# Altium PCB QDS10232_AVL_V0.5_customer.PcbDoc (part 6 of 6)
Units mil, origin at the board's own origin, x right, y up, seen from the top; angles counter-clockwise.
Board outline 3500 x 3799 mil, 6 copper layers (Top Layer, GND, INT1, PWR1, PWR2, Bottom Layer), stack 78.834 mil thick; 254 components, 204 nets, 7039 pads, 595 vias.
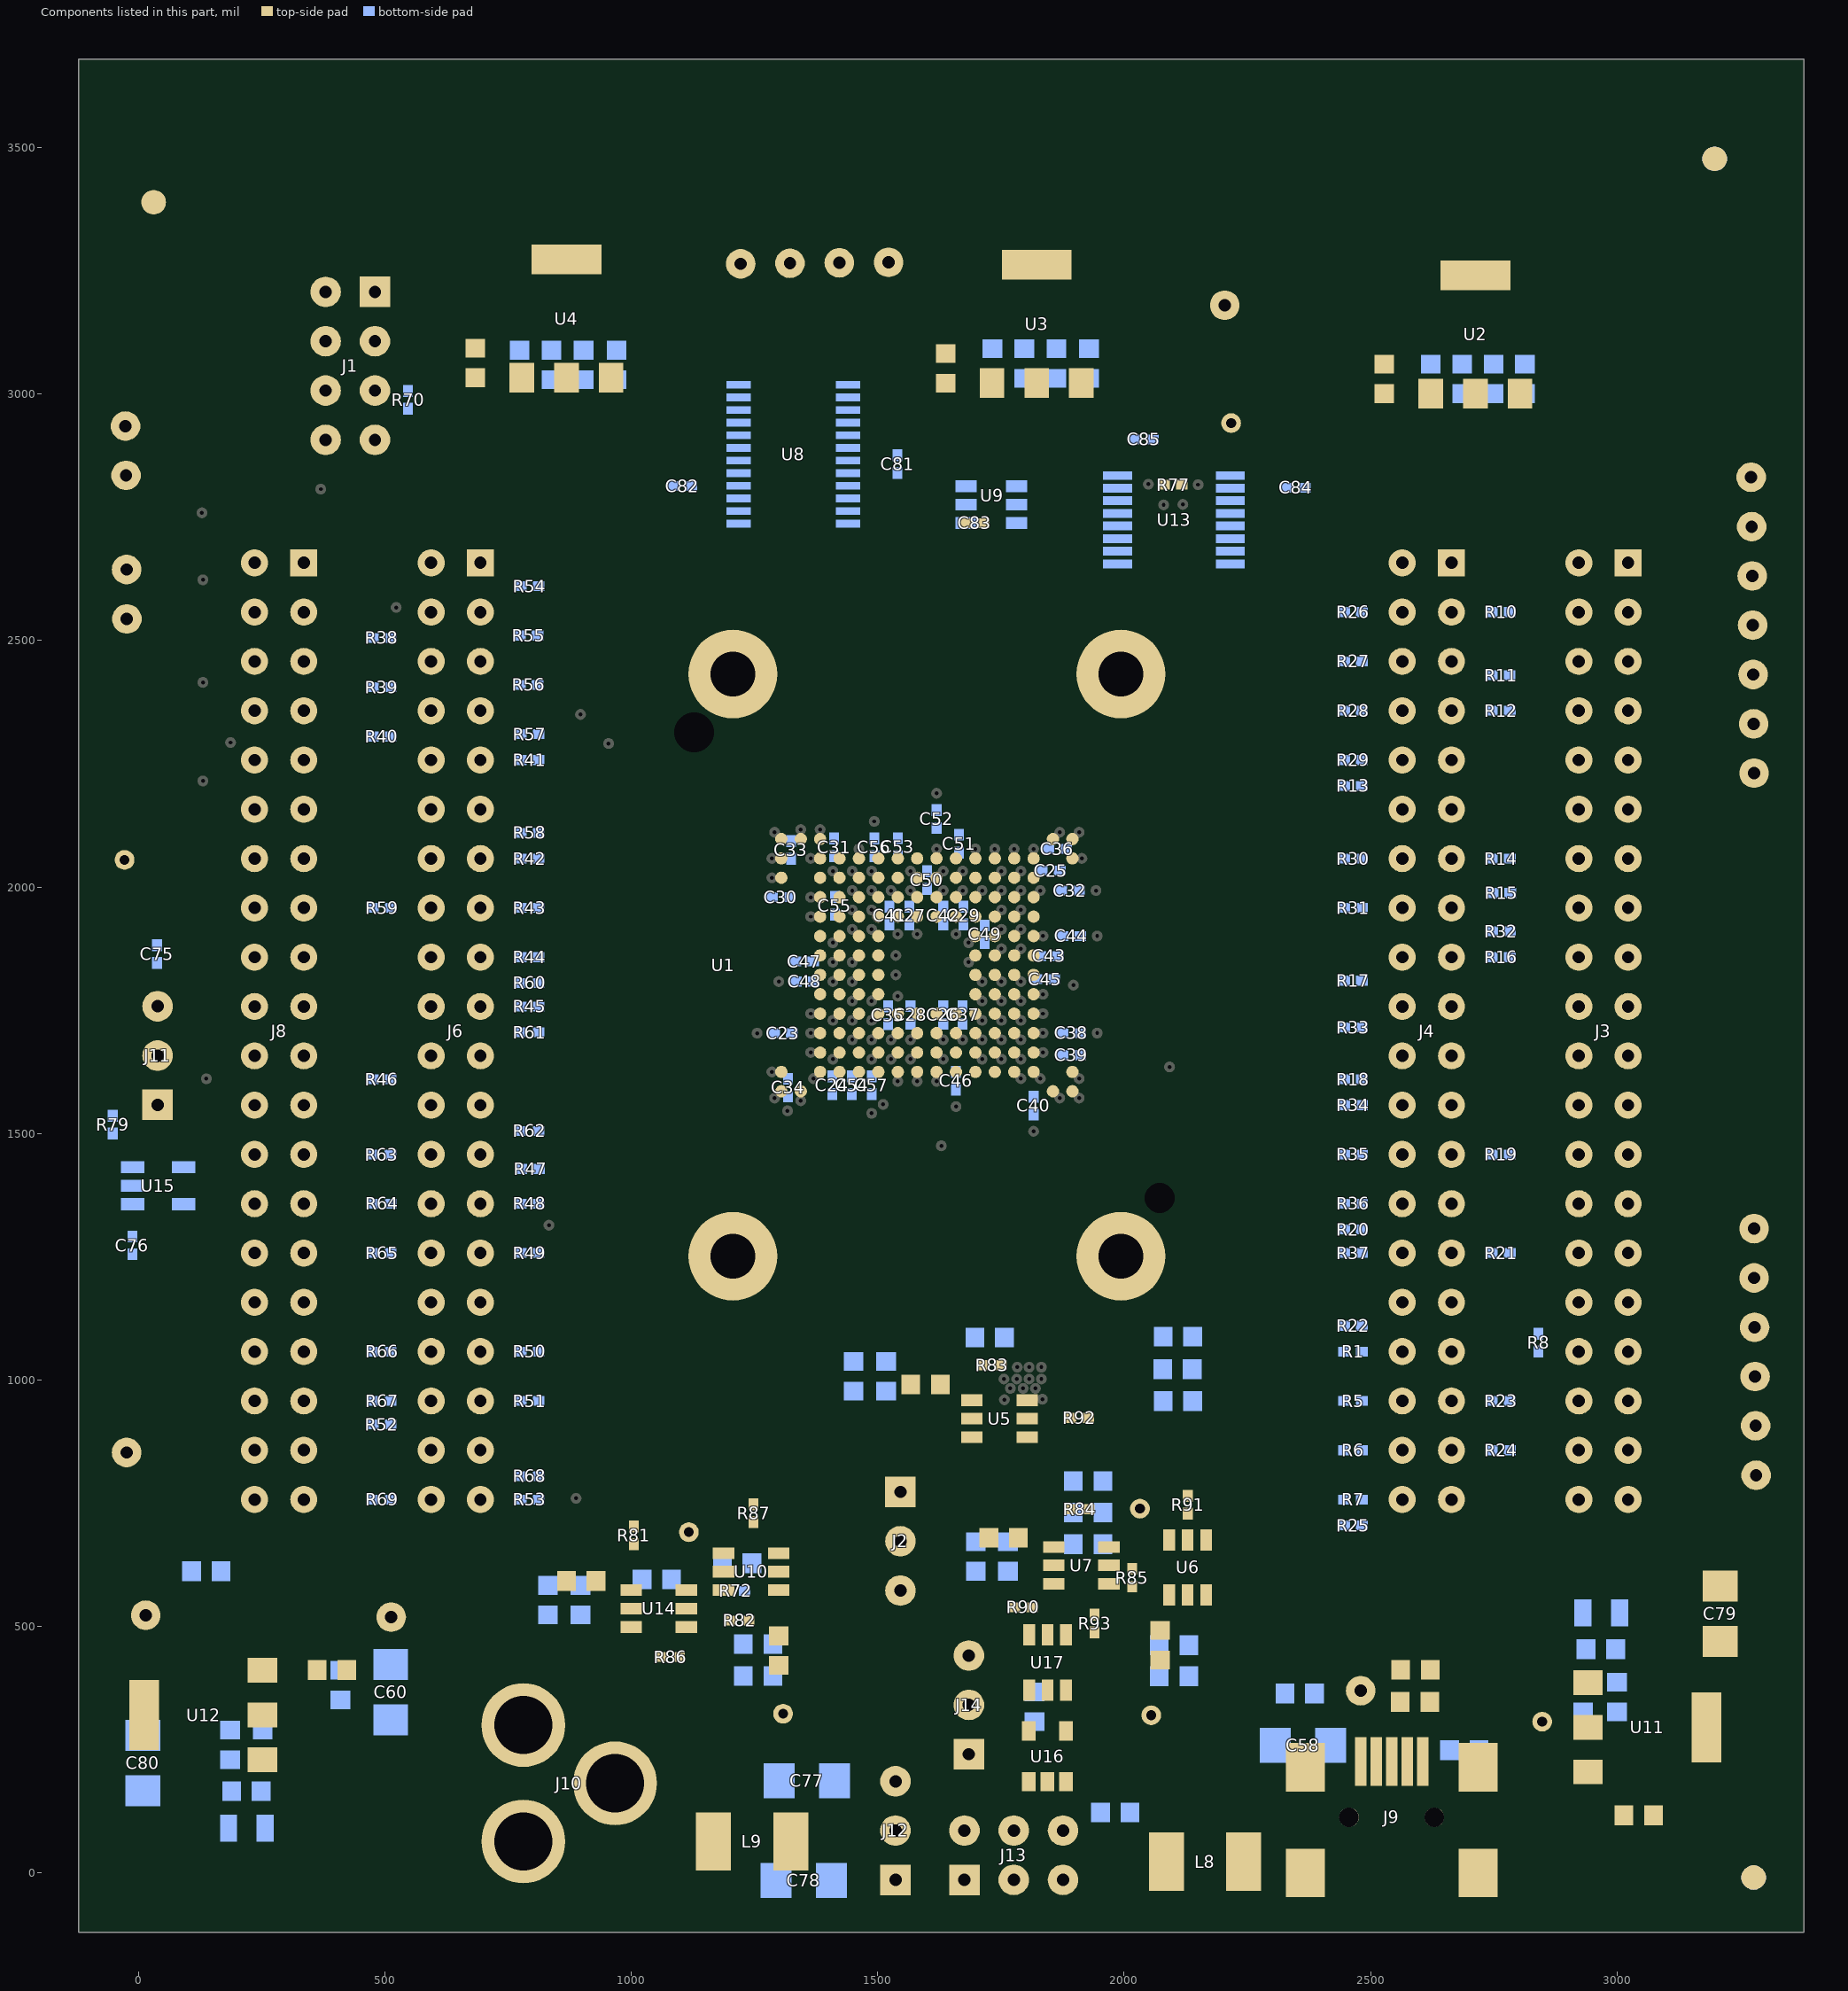
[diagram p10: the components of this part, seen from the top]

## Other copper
Top Layer:
  rectangle net VCCIO: 1267,282 1407,440
  region net VCC_REG: 3132,58 3265,191 3201,255 3068,122
  rectangle net VCC_REG: 3055,58 3133,198
  rectangle net NetL6_2: 2954,58 3035,147
  region net VCC_M: 2009.5,628.5 2024,643 1996.5,670.5 1982,656
  rectangle net VCC_M: 2003,605 2103,658
  rectangle net NetL2_1: 2003,471 2103,596
  rectangle net NetL3_2: 1765,651 1904,810
  rectangle net NetL5_1: 1225,461 1330,585
  region net VCCQ: 1166,535 1190,559 1156,593 1132,569
  rectangle net VCCQ: 1162,461 1214,582
  region net VCCQ: 1074.5,654.5 1098,678 1055.5,720.5 1032,697
  region net VCCQ: 1043,701 1093.5,751.5 1059,786 1008.5,735.5
  rectangle net VCCQ: 982,690 1088,740
  rectangle net VCCIO: 1381,737 1589,1043
  rectangle net VCC_M: 1738,947 1847,1043
  rectangle net NetL1_2: 1606,947 1727,1043
  region net VCC_REG: 3121,342 3216,437 3161,492 3066,397
  rectangle net VCC_REG: 3146,396 3269,505
  rectangle net VCC: 2105,2760 2166,2836
  rectangle net VCC_M: 2036,2760 2093,2836
  rectangle net NetJ9_6: 2329,87 2364,179
  rectangle net NetJ9_6: 2203,-49 2367,116
  rectangle net VCC_REG: 2813,258 3037,332
  region net GND: 1432,146 1283,146 1283,-25 1432,-25
  region net GND: 2143,114 1994,114 1994,-57 2143,-57
  rectangle net NetL6_2: 2803,58 2972,229.9
  rectangle net NetL6_2: 166,378 383,556
  rectangle net GND: 2147,193 2282,321
  rectangle net GND: 2147,302 2281,392
  rectangle net VCC_M: 1381,632 1589,716
  rectangle net VCC_REG: 3015,186 3270,405
  rectangle net VCCQ: 1059,694 1212,786
  rectangle net NetL4_2: 909,562 1027,681
  rectangle net GND_EXT: 383,142 609,346
  rectangle net VCCIO_REG: -39,243 115,554
  rectangle net +5V_EXT/(+3): 403,378 615,555
  rectangle net VCCIO_REG: 751,561.4 887.82,671.4
  rectangle net VCCEXT: 1972,152 2107,451
  rectangle net VCC_REG: 1619,649 1745,811
  rectangle net VCC_M: 1916,650 2103,810
  rectangle net GND: 1490,1810 1547,1873
  pour cut-out: 1240,732 1294.45,755.38 1285,720 1248,712
  pour cut-out: 1323,637 1318,595 1242,593 1245,612 1267,636
  pour cut-out: 1000,451 1043,429 1077,439 1114,482 1071,502 1004.64,483.2
  pour cut-out: 1014,562 958,559 945,545 979,507 1018,456 1046,455 1061,465.98 1063,557 1040,578
  pour cut-out: 654.21,615.79 628,551 693,548 687.33,582.67
  pour cut-out: 980,549 947,553 912,540 911,499 961,485 996,492 1012,525
  pour cut-out: 1450,624 1457,585 1477,590 1487,619 1472,626
  pour cut-out: 1821,376 1914.4,371 1933,362 1909,299 1867,255 1812,256 1806.9,326.07
  pour cut-out: 1846,644 1848,602 1886,606 1894,630 1875,651
  pour cut-out: 1951,505 1966,451 1981,465 1968,510
  pour cut-out: 1938,508 1896,474 1896,508 1920,519
  pour cut-out: 1478.64,1584.64 1670.7,1584.3 1651,1637 1526,1636
  pour cut-out: 1860.43,1821.76 1851,1600 1802.95,1559.46 1737.5,1564.16 1753,1663 1776.87,1703.65 1815,1799
  pour cut-out: 1859,2018.61 1859,1861.13 1826,1877 1844,1996
  pour cut-out: 1718,2100.12 1820,2099 1848.72,2018.61 1751.06,2032.18 1718,2052.72
  pour cut-out: 1588,2103 1678.76,2104.76 1658.76,2084.76 1580.02,2083.27
  pour cut-out: 1533.86,1986.03 1422.54,1979.24 1396,1895 1438,1750 1455.12,1736.24 1533.86,1696.87 1726,1687 1783.65,1696.87 1799,1771 1777,1919 1751.06,1992.81 1632.95,1992.81
  pour cut-out: 566.46,1257.56 547,1211 596,1219 604,1228
  pour cut-out: 456,1344 475,1303 439,1321 440,1331
  pour cut-out: 208.19,1257.56 191,1219 227,1215 235.69,1230.06
  pour cut-out: 193,1301 204,1268 229,1279 229,1305
  pour cut-out: 453,1301 446,1268 433,1248 394,1242 426,1331
  pour cut-out: 216.25,1338.11 199,1317 281,1313 360,1313 344,1341 242,1352
  pour cut-out: 355.14,1238.11 383,1213 392,1228 377,1251
  pour cut-out: 1124,479 1154,459 1155,476 1128.65,487.19
  pour cut-out: 2438,1296 2403,1268 2395,1247 2408,1215 2448,1246 2455,1279
  pour cut-out: 2413,1342 2438,1310 2447,1348 2411.64,1357.56
  pour cut-out: 2362,1469 2415,1469 2447,1437 2438,1428 2412,1428 2403,1419 2382,1440 2373,1440
  pour cut-out: 2615,2964 2634,2938 2641,2943 2638,2963
  pour cut-out: 2546,3029 2589,3043 2599,3003 2589,2960 2543,2977
  pour cut-out: 2636,3038 2682,3053 2685,3030 2668,3010 2651,3013
  pour cut-out: 1724,2984 1749,2949 1754,2990
  pour cut-out: 1754,3061 1792,3073 1790,3052 1761,3041
  pour cut-out: 766,2997 795,2968 801,2992 790,3003
  pour cut-out: 698,3059 744,3074 747,2992 703,3009 699,3035
  pour cut-out: 794,3074 838,3084 834,3060 799,3054
  pour cut-out: 805,1898.92 721,1848 746,1825 808,1843 814,1875
  pour cut-out: 2369,2249 2401,2216 2467,2200 2458,2245 2411.64,2257.56
  pour cut-out: 2898,2545 2859,2516 2899,2461 3014,2459 3047,2465 3073,2506 3053,2545 3013,2555 2922.31,2557.56
  pour cut-out: 2977,423 3024,413 3003,394 2957,403
  pour cut-out: 2877,375 2855,339 2904,337 2912,353
  pour cut-out: 2120,961 2100,923 2072,947 2083,962
  pour cut-out: 189,289 212,248 308,248 290,298 227,306
  pour cut-out: 211,1049 178,1009 176,986 253,961 284,996 296,1028 252,1056
  pour cut-out: 385,1409 347,1376 344,1345 404,1337 413,1363
  pour cut-out: 382,1500 344,1477 343,1440 387,1417 397,1469
  pour cut-out: 458,1568 487,1557 477,1530 450,1528 441.52,1546.52 448,1563
  pour cut-out: 512,1479 605,1454 669,1456 693.96,1457.56 736,1503 671,1529 523,1534
  pour cut-out: 743,1502 786,1463 823,1481 796,1528
  pour cut-out: 861,1415 850,1368 844,1345 791,1304 789,1389 819,1431
  pour cut-out: 565,1348 545,1312 543,1297 566,1272 604,1293 601,1328
  pour cut-out: 624,1348 692,1347 696,1313 601,1306 608,1342
  pour cut-out: 716,1341 779,1339 779,1323 712,1331
  pour cut-out: 731,1201 753,1156 794,1175 803,1206 754,1220
  pour cut-out: 483,1151 504,1119 480,1106 466,1135
  pour cut-out: 97,564 173,565 161,534 138,518 100,522
  pour cut-out: 321,376 286,333 267,364 274,386
  pour cut-out: 356,377 377,333 396,340 396,378
  pour cut-out: 878,343 947,278 899,248 846,285
  pour cut-out: 836,460 797,420 787,449 802.6,467.4
  pour cut-out: 810,561 788,523 772,505 759,546 783,567
  pour cut-out: 714,667 756,633 768,681 755,701 719,702 709,686
  pour cut-out: 900,730 928,630 852,618 867,707
  pour cut-out: 1054,661 1012,626 1006,564 1084,533 1093,596 1080,638
  pour cut-out: 1223,696 1225,666 1214,665 1210,674
  pour cut-out: 1645,649 1588,591 1538,647 1577,668
  pour cut-out: 1583,857 1640,816 1622,773 1546,773
  pour cut-out: 2825,53 2756,6 2760,49 2795,63
  pour cut-out: 3044,181 2967,149 2975,191 3014,197
  pour cut-out: 2810,304 2751,273 2757,241 2801,241 2819,255
  pour cut-out: 2681,296 2702,270 2690,257 2673,270
  pour cut-out: 2667,281 2620,280 2616,174 2680,172 2674,273
  pour cut-out: 2578,179 2674,179 2673,170 2572,171
  pour cut-out: 2376,300 2356,266 2397,263 2403,288
  pour cut-out: 2591,390 2592,380 2589,376 2587,382
  pour cut-out: 2504,475 2550,442 2533,424 2491,433
  pour cut-out: 2966,800 2933,775 2919,746 2949,694 2981,726 2974,772
  pour cut-out: 2898,950 2871,915 2869,898 2892,865 2940,861 2975,918 2940,943 2929,950
  pour cut-out: 2523,807 2547,761 2657,767 2711,812 2710,820 2687,850 2643,852 2544,855 2515,817
  pour cut-out: 2443,810 2414,767 2394,792 2402,812
  pour cut-out: 2430,852 2443,821 2432,813 2409,837
  pour cut-out: 2356,914 2327,891 2360,876 2368,901.2
  pour cut-out: 2407,1039 2368,1033.6 2380,1054 2398,1056
  pour cut-out: 2584,1545 2671,1547 2692,1543 2707,1511 2724,1475 2664.04,1457.56 2579,1454 2532,1467 2513,1506 2568,1537
  pour cut-out: 2532,1544 2515,1519 2561,1513 2562,1544
  pour cut-out: 2352,1565 2401,1572 2431,1553 2443,1515 2380,1536
  pour cut-out: 2213,1572 2176,1505 2242,1504 2244,1540
  pour cut-out: 1323,1761 1322,1687 1360,1691 1368,1733 1351,1766
  pour cut-out: 1308,1839 1251,1827 1266,1786 1349,1778 1375,1813
  pour cut-out: 1325,1675 1376,1550 1406.27,1608.65 1383.17,1664.28 1361,1677
  pour cut-out: 1203,1551 1222,1513 1180,1515 1184,1538 1190,1551
  pour cut-out: 1503,2158 1467,2155 1458.14,2124.86 1491,2094 1531,2101 1521,2148
  pour cut-out: 1383,2074 1417,2096 1417,2074 1398,2060
  pour cut-out: 1344,2062 1323,2022 1338.61,2018.61 1360.89,2018.61 1374,2048
  pour cut-out: 1155,1950 1171,1899 1197,1920 1193,1962
  pour cut-out: 853,1943 812,1920 815,1952 832,1955
  pour cut-out: 539,1796 566,1763 608,1756 683,1756 713,1757 760,1781 738,1808 578,1803
  pour cut-out: 532,1833 583,1847 678,1853 723,1846 742,1812 645,1805 542,1805
  pour cut-out: 460,1960 454,1905 426,1927 433,1961
  pour cut-out: 835,2101 787,2112 803,2126 827,2126
  pour cut-out: 786,2194 796,2162 824,2175 818,2198
  pour cut-out: 330,2534 332,2477 359,2507 346,2533
  pour cut-out: 924,2636 875,2643 827,2619 882,2560 955,2622
  pour cut-out: 1482,2726 1433,2716 1440,2731 1469,2748
  pour cut-out: 1398,2893 1374,2890 1357,2859 1395,2829 1426,2837 1424,2880
  text "TOP" at 4320,1517 h65
GND:
  text "GND1" at 4328,1218.56 h65
PWR1:
  text "POWER 1" at 5601,1219 h65
INT1:
  pour cut-out: 2685,618 2738,600 2832,499 2832,-97 2803,-104 2805,-21 2782,-7 2791,16 2808,33 2805,414 2681,578 2686,608
  pour cut-out: 2271,191 2247,150 2267,136 2289,138 2295,146 2295,162 2290,170 2278,173 2277,184
  pour cut-out: 2274,476 2290,466 2293,452 2289,443 2282,437 2270,433 2255,447 2256,464 2270,477 2271,477
  pour cut-out: 2270,592 2270,538 2297,541 2301,552 2301,564 2296,571 2290,575 2276,575
  pour cut-out: 1348,777 1312,741 1333,722 1359,729 1364,744 1358,758 1349,770
  pour cut-out: 1938,951 1999,951 1995,909 1960,903 1941,939
  pour cut-out: 2156.73,1007.27 2117,939 2184,944 2186,972
  pour cut-out: 2583,744 2575,661 2479,678 2540,744
  pour cut-out: 1959,1637 1888,1640 1896,1569 2148,1546 2240.76,1537 2239,1617 2116,1662
  pour cut-out: 906,2383 797,2316.56 797,2373.95 870,2416
  pour cut-out: 1918.96,1931 1919.82,1868 1862,1868 1859,1910
  pour cut-out: 1693,1945 1617,1929.66 1627,1765 1653,1722 1709,1721 1771,1745.51 1772,1898 1771,1934.01
  pour cut-out: 1467.78,1959.35 1390,1908 1418.7,1867 1498.32,1856.32 1534,1927
  pour cut-out: 1513,1852 1448.34,1808.2 1461.66,1742.78 1455,1683 1527.08,1690.09 1563,1719 1582.5,1838.5 1573,1851
  pour cut-out: 2091.14,1662 2067,1654 2061,1617 2115.13,1608 2124,1622 2116,1662
  pour cut-out: 1969.79,1608 1956.65,1537 1837,1579 1879,1646 1904,1642
  pour cut-out: 2029,1441 2035,1401 2093.72,1390.58 2111,1425 2109,1456
  pour cut-out: 2899,1254 2873,1211 2958.93,1195.07 2955,1256
  pour cut-out: 2895,1554 2866.88,1508 2855,1491 2915,1464 2941,1457 2963,1507 2956,1540
  pour cut-out: 2933,1582 2970,1606 3016,1589 3018,1533 2970,1519 2936,1522 2938,1564
  pour cut-out: 2976,1801 3014,1784 3015,1735 2979,1713 2965,1760
  pour cut-out: 2878,1708 2967,1709 2964,1732 2880,1732
  pour cut-out: 2442,2094 2417,2072 2416,2042 2425,1968 2448,1972 2445,2079
  pour cut-out: 2365,2349 2388,2300 2421,2393 2402,2410 2372,2367
  pour cut-out: 2408,2186 2438,2162 2443,2190 2435,2212
  pour cut-out: 2780.64,2465.28 2792,2376 2817,2401 2819,2446
  pour cut-out: 2847.22,2326.78 2778,2305 2787,2347 2816.44,2357.56
  pour cut-out: 2507,2495 2535,2455 2575,2457 2648,2453 2693,2455 2721,2500 2590,2515
  pour cut-out: 2467,2495 2439.32,2429.88 2411.64,2457.56 2431,2495
  pour cut-out: 2364,2548 2405,2501 2425,2559 2386,2566
  pour cut-out: 885,2644 873,2591 846,2627 849,2650
  pour cut-out: 385,1211 189,1209 208,1245 344,1244 389,1235 374,1223
  pour cut-out: 446,1239 414,1214 419,1247 430,1253
  pour cut-out: 416,1098 446,1077 441.56,1057.56 439,1040 417,1019 408,1060 409,1070
  pour cut-out: 192,1106 230,1087 292,1099 330,1086 319,1056 214,1062 192,1069 191,1084
  pour cut-out: 369,1085 390,1102 385,1063 362,1049 348,1069 362,1079
  pour cut-out: 421,992 447,974 429,965 412,973
  pour cut-out: 438,900 383,876 390,908 406,925
  pour cut-out: 2512,999 2535,965 2565,983 2547,1008
  pour cut-out: 2715,1010 2694,967 2673,983 2674,995
  pour cut-out: 2749,1021 2768,996 2840,1008 2817,1031 2771,1031
  pour cut-out: 2519,1014 2552,1046 2572,1050 2677,1052 2725,1031 2711,1010 2576,994
  pour cut-out: 2510,1307 2547,1350 2664.04,1357.56 2723,1310 2677,1278 2555,1281
  pour cut-out: 2514,1508 2547,1464 2669,1464 2687,1467 2711,1519 2629,1546
  pour cut-out: 1886,1906 1901,1872 1859,1868 1855.5,1890.5
  pour cut-out: 1489,1613 1530,1599 1529,1622 1512.72,1636.36
  pour cut-out: 1339,1642 1330,1634 1353,1607 1378,1598 1417,1614 1372,1657
  pour cut-out: 1307,1676 1349,1730 1408.97,1729.46 1420,1704 1390,1654 1327,1654
  pour cut-out: 1781,1557 1757,1518 1742,1535 1734,1558 1769,1572
  pour cut-out: 1904,1657 1882,1613 1841,1633 1851,1660 1873,1674
  pour cut-out: 1910,1597 1832.8,1586 1841,1538 1893,1546 1937,1556 1939,1585
  pour cut-out: 2436,1497 2421,1459 2400,1488 2416,1500 2428,1507
  pour cut-out: 648,512 600,491 594,431 712,362 695,464 679,507
  pour cut-out: 716,1706 759,1680 782,1712 760,1734
  pour cut-out: 1407,2974 1471,2951 1475,2936 1450.5,2930.5 1399,2948
  pour cut-out: 1267,2918 1234,2917 1227,2865 1288,2852 1314,2882 1308,2910
  pour cut-out: 1392,2892 1352.64,2876.49 1372.82,2839 1404.5,2839 1423,2861
  pour cut-out: 517,2498 476,2494 482,2425 560,2422 593.96,2457.56 573,2498
  pour cut-out: 936,2803 963,2769 915,2767 920,2791
  pour cut-out: 545,2867 575,2824 533,2821 527,2837
  pour cut-out: 236,2528 236,2484 260.35,2482.21 258,2534
  pour cut-out: 233,2433 233,2385 249,2388 259,2430 251,2436
  pour cut-out: 228,2332 227,2280 251,2291 250,2336
  pour cut-out: 459,2361 515,2346 505,2321 451,2312
  pour cut-out: 252,2239 294.5,2199.5 295,2243 261,2248
  pour cut-out: 419,2249 460,2234 465,2275 424,2270
  pour cut-out: 275,2106 237,2079 321,2052 327,2068 294,2104
  pour cut-out: 231,2036 234,1976 250,1989 245,2037
  pour cut-out: 232,1932 233,1883 251,1891 259,1932
  pour cut-out: 263,1859 304,1858 310,1867 271,1870 257,1863
  pour cut-out: 390,1911.87 438,1868 449,1901 410,1923
  pour cut-out: 832,2498 783,2484 795,2508 831,2509
  pour cut-out: 1072,2321 1025,2300 1187,2224 1209,2230 1172,2281
  pour cut-out: 1078,2207 1060,2178 1095,2177 1098,2194
  pour cut-out: 1527,2133 1495,2098 1520,2088 1541,2101 1533,2130
  pour cut-out: 1600,2142 1643,2150 1646,2130 1612,2121
  pour cut-out: 1654,2118 1760,2106 1737.5,2077.17 1666,2088
  pour cut-out: 1829,2069 1839,2033 1790.43,2032.18 1794,2049
  pour cut-out: 1872,2017 1876,1965 1854,1960 1846,1991 1856,2011
  pour cut-out: 1864,1904 1886,1869 1853,1859 1845,1887
  pour cut-out: 1938,1742 1887,1720 1939,1667 1991,1682 2004,1717 1985,1745
  pour cut-out: 2156,1872 2180,1832 2130,1834 2131,1845
  pour cut-out: 2527,2002 2537,2040 2586,2060 2713,2056 2744,2036 2650,1985 2543,1994
  pour cut-out: 2787,2107 2876,2103 2870,2077 2777,2088
  pour cut-out: 2793,1799 2863,1769 2857,1830 2796,1827
  pour cut-out: 2833,1209 2801.29,1166.98 2791,1200 2799,1215
  pour cut-out: 3050,1055 3093,1032 3085,1018 3036,1025
  pour cut-out: 2896,949 2874,908 2947,912 2946,934
  pour cut-out: 2901,1050 2873,1017 2893,975 2918,980 2928,1020
  pour cut-out: 2965,1109 2929,1077 2968,1068 2973,1083
  pour cut-out: 2685,960 2709,902 2691,868 2638,910
  pour cut-out: 2518,898 2535,871 2551,871 2572,926 2562,943 2521,918
  pour cut-out: 2502,796 2537,758 2643,747 2698,756 2718,800 2689,853 2577,862 2529,851 2509,802
  pour cut-out: 663,583 640,544 666,518 701,532 696,556
  pour cut-out: 892,377 857,324 826,373 846,390
  pour cut-out: 189,1408 208,1448 248,1460 335.69,1457.56 321,1395 243,1376
  pour cut-out: 353,1569 441.52,1610 448,1581 372,1532
  pour cut-out: 328,1489 335,1538 355,1518 359,1470 354,1462
  pour cut-out: 858,1043 880,1006 935,979 936,1033 885,1064
  pour cut-out: 901,689 888,639 863,657 867,671
  pour cut-out: 873,625 793,577 788,609 812,635
  pour cut-out: 794,567 777,514 739,549 750,566
  text "INTERNAL1" at 4341,1369 h65
PWR2:
  text "POWER 2" at 5603,1063 h65
Bottom Layer:
  rectangle net VCCEXT: 1440,336 1604,609
  rectangle net VCCIO: 1266,282 1407,520
  region net VCCIO_REG: 114,243 147,276 130,293 97,260
  region net +5V_USB/(+3): 2618,259 2678,319 2592,405 2532,345
  rectangle net VCCIO: 1381,738 1589,999
  rectangle net GND_EXT: 387,137 615,370
  rectangle net VCC: 2106,2760 2166,2836
  rectangle net VCC_M: 2036,2760 2091,2836
  rectangle net NetL6_2: 149,379 370,635
  rectangle net GND: 2115,178 2346,321
  rectangle net GND: 2248,303 2346,392
  region net GND: 2226,256 2305,335 2248,392 2169,313
  rectangle net VCC_M: 1400,632 1589,716
  rectangle net +5V_USB/(+3): 2366,289 2609,533
  rectangle net VCC_REG: 3044,325 3268,405
  rectangle net VCC_REG: 3007,186 3268,343
  region net VCCIO_REG: 142,298 167.5,323.5 107,384 81.5,358.5
  rectangle net VCCIO_REG: -41,243 128,635
  rectangle net GND: 1225,603 1360,652
  rectangle net GND_EXT: 458,235 569,343
  rectangle net GND_EXT: 387,291 435,370.56
  rectangle net +5V_EXT/(+3): 390,388 616,560
  rectangle net VCCIO_REG: 63,269 288,338
  rectangle net VCC_REG: 2823,261 3152,346
  rectangle net +5V_USB/(+3): 2368,177 2679,320.45
  rectangle net GND: 752,3070 1003,3168
  rectangle net GND: 2580,3045 2851,3132
  rectangle net GND: 1695.39,3064 1968,3184
  rectangle net GND: 1204.82,366.4 1246.82,520.4
  rectangle net VCCQ: 1060.82,545.4 1205.82,785
  rectangle net VCCIO_REG: 752,563.4 939.82,661.4
  rectangle net GND: 804.82,496.4 972.53,545.4
  rectangle net GND: 2112,361 2178,536
  rectangle net GND: 1662,584 1829.71,633
  rectangle net VCC_REG: 1617,651 1797,812
  rectangle net GND: 1835,647 1916,819
  rectangle net GND: 1509,1746 1696,1936
  rectangle net VWR: 752,2952.93 1002.7,3062.93
  rectangle net VDD: 1703.7,2941.93 1956.7,3051.93
  rectangle net VPPW: 2593.7,2920.64 2846.7,3030.64
  pour cut-out: 1433,552 1401,532 1419,511 1430,509 1436,521
  pour cut-out: 1459,324 1411,300 1415,331 1438,330
  pour cut-out: 2694,1560 2732,1508 2705,1495 2658,1526
  pour cut-out: 2638,1950 2616.48,1910 2668,1910 2670,1932
  pour cut-out: 2837,1902 2835,1864 2819,1874 2817,1893
  pour cut-out: 2826,1980 2825,1916 2799,1939 2817,1974
  pour cut-out: 1683,1718 1752,1704 1751.06,1690.09 1672.32,1690.09
  pour cut-out: 1762,1773 1765,1701 1783,1700 1796,1750 1790.43,1768.83
  pour cut-out: 1714,1908 1740,1874 1760,1892 1763,1916
  pour cut-out: 1455,1792 1413,1791 1418,1808 1433,1816
  pour cut-out: 1368,1755 1448,1745 1419,1713 1358,1718
  pour cut-out: 645,1497 663,1461 683,1467 695,1496
  pour cut-out: 856,1488 854,1443 829,1458 836,1488
  pour cut-out: 753,1599 764,1518 724,1537 726,1579
  pour cut-out: 512,1656 496,1626 535,1618 552,1627
  pour cut-out: 177,1752 260,1766 351,1757 386,1715 278,1711 182.5,1733.5
  pour cut-out: 294,1901 316,1865 358,1865 399,1896 360,1919 315,1917
  pour cut-out: 403,1982 252,1975 272,1942 416,1947
  pour cut-out: 538,1892 561,1858 581,1871 579,1898
  pour cut-out: 581,1837 578,1780 601,1785 605,1820
  pour cut-out: 867,1846 870,1762 836,1789 838,1833
  pour cut-out: 906,1880 864,1862 859,1892
  pour cut-out: 908,1992 901,1916 874,1924 889,1994
  pour cut-out: 1240,1883 1205,1839 1183,1875 1220.06,1886.94
  pour cut-out: 1023,2096 1007,2066 1049.44,2057.56 1061,2071
  pour cut-out: 865,2096 882,2065 833,2085 833,2097
  pour cut-out: 2530,1855 2486,1820 2611.6,1810 2589,1851 2564.04,1857.56
  pour cut-out: 2469,1798 2485,1757 2506.56,1757.56 2514,1790
  pour cut-out: 2650,1739 2578,1756 2639,1761 2664.04,1757.56
  pour cut-out: 2688,1839 2679,1785 2651,1801 2661,1843
  pour cut-out: 2581,2270 2638,2271 2637,2245 2588,2240
  pour cut-out: 2035,2903 2070,2836 2000,2839 2003,2890
  pour cut-out: 1634,2722 1587,2717 1589,2733 1626,2739
  pour cut-out: 1110,2873 1100,2832 1132,2832 1143,2847
  pour cut-out: 1182,2725 1158,2660 1205,2662 1217,2708 1211,2721
  pour cut-out: 1573,2701 1582,2663 1552,2664 1548,2679
  pour cut-out: 1274,2723 1333,2715 1331,2731 1297,2748
  pour cut-out: 1377,2824 1331,2805 1357,2791 1386,2794
  pour cut-out: 1502,2730 1520,2708 1494,2689 1466,2710 1470,2726
  pour cut-out: 1415,2886 1418,2845 1541,2853 1501,2887 1463.86,2890.54
  pour cut-out: 573,2566 522,2522 573,2504 612,2514
  pour cut-out: 716,2657 771,2626 742,2609 717,2620
  pour cut-out: 776,2602 776,2522 732,2538 749,2593
  pour cut-out: 776,2499 774,2423 753,2427 753,2490
  pour cut-out: 767,2401 776,2310 730,2323 759,2400
  pour cut-out: 511.92,2305.12 567,2249 591,2288 575,2304
  pour cut-out: 536,2487 465,2476 477,2431 571,2417 585,2451
  pour cut-out: 291,287 313,247 299,240 263,257
  pour cut-out: 322,374 297,331 265,358 278,377
  pour cut-out: 673,227 611,196 628,229 653,239
  pour cut-out: 1595,855 1634,814 1602,812 1585,829
  pour cut-out: 3042,184 2988,145 2981,186
  pour cut-out: 2374,171 2374,-20 2715,-19 2710,169 2656,175 2494,197 2408,188
  pour cut-out: 2639,87 2720,61 2698,99
  pour cut-out: 2578,177 2597,133 2638,127 2624,182
  pour cut-out: 2655,352 2713,348 2703,324 2683,322 2663,332
  pour cut-out: 2874,390 2781,352 2806,330 2879,339 2910,363
  pour cut-out: 2590,772 2643,772 2641,747 2583,743
  pour cut-out: 2591,1041 2645,1043 2639,1064 2598,1070
  pour cut-out: 2396,1113 2411.64,1057.56 2441,1080 2428,1110
  pour cut-out: 2662,931 2657,871 2690,883 2695,935
  pour cut-out: 2611.6,1305.12 2585,1259 2572,1297
  pour cut-out: 2389,1319 2395,1264 2424,1273 2428.94,1305.12
  pour cut-out: 2712,1394 2695,1363 2681,1382 2686,1403
  pour cut-out: 2771,1443 2748,1399 2731,1422 2733,1445
  pour cut-out: 2822,1441 2856,1415 2847,1452 2816.44,1457.56
  pour cut-out: 1745,1860 1740,1813 1762,1812 1778,1845
  pour cut-out: 1575,1745 1622,1745 1616,1723 1577,1719
  pour cut-out: 1710,1638 1672,1622 1677,1641 1696,1649
  pour cut-out: 1899,1691 1898,1675 1881,1675 1879,1684
  pour cut-out: 1808,2123 1831,2089 1794,2093 1776.87,2103.87
  pour cut-out: 1864,2062 1854,2043 1849,2054 1854,2063
  pour cut-out: 1917,1942 1892,1909 1873,1933 1892,1944
  pour cut-out: 1891,1986 1913,1964 1888,1953 1867,1970
  pour cut-out: 1632,2108 1655,2090 1638,2083 1630,2087
  pour cut-out: 1353,2075 1394,2085 1403,2073 1395,2059 1363.98,2057.98
  pour cut-out: 1420,2081 1452,2093 1449,2073 1439,2066 1430,2068
  pour cut-out: 1503,2087 1530,2087 1525,2074 1499,2075
  pour cut-out: 1399,1970 1400,1919 1363,1927 1369,1963 1398,1988
  pour cut-out: 1303,2039 1298,1994 1338,1993 1332,2019 1324,2040
  pour cut-out: 1302,1976 1283,1950 1304,1949 1324,1953
  pour cut-out: 1319,1879 1354,1854 1359,1881
  pour cut-out: 1464,1724 1491,1706 1478,1696 1458,1703
  pour cut-out: 1527,1745 1555,1745 1555,1736 1536,1730
  pour cut-out: 1502,1592 1540.65,1575.19 1538,1594 1509,1619
  pour cut-out: 1288,1655 1302,1625 1325,1634 1318,1658
  pour cut-out: 1306,1694 1288,1679 1295,1668 1319,1672
  pour cut-out: 1190,1655 1166,1624 1146,1636 1146,1652
  pour cut-out: 1103,1654 1080,1611 1136,1612 1131,1628
  pour cut-out: 1034,1755 999,1707 1061,1700 1068,1715
  pour cut-out: 869,1736 876,1714 853,1709 839,1737 847,1746
  text "BOTTOM" at 5635,1519 h65

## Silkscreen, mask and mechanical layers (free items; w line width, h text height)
Top Overlay:
  drawing of 1923 lines, arcs and shapes, not listed
  text "PN: LAT PARALLEL AVA V2_REV0.5" at 1233,3595 h50
  text "GND" at 2159,3239 h40
  text "VWR" at 1178,3210 h40 r270
  text "GND" at 1300,3209 h40 r270
  text "GND" at 1506,3207 h40 r270
  text "VDD" at 1402,3204 h40 r270
  text "5" at 276,3190 h35
  text "1" at 560,3190 h35
  text "DQ0" at 34,2917 h40
  text "8" at 279,2887 h35
  text "4" at 567,2881 h35
  text "GND" at 32,2817 h40
  text "VCCQ" at 3069,2811 h40
  text "J8" at 241,2743 h55
  text "J6" at 599.27,2743 h55
  text "J4" at 2569.35,2743 h55
  text "J3" at 2927.61,2743 h55
  text "GND" at 3114,2708 h40
  text "VCC_M" at -77,2703 h40
  text "GND" at 3115,2608 h40
  text "GND" at 36,2523.02 h40
  text "VPPW" at 3080,2515 h40
  text "GND" at 3117,2408 h40
  text "A0" at 3148,2310 h40
  text "GND" at 3119,2208 h40
  text "GND" at 32,2037.02 h40
  text "VCC_M" at -54,1848.33 h40
  text "GND" at -10.48,1438.4 h40
  text "GND" at 3119,1284 h40
  text "E#" at 3155,1190 h40
  text "GND" at 3120,1084 h40
  text "W#" at 3143,987 h40
  text "GND" at 3122,884 h40
  text "GND" at 36,835 h40
  text "G#" at 3159,787 h40
  text "1" at 1608,756 h35
  text "TOP SILKSCREEN" at 4302,613 h65
Bottom Overlay:
  drawing of 1758 lines, arcs and shapes, not listed
  text "QHO@QDESIGNSERVICES.COM" at 2883.8,3501.89 h30
  text "TEL: 408-375-8527" at 2885.54,3450.39 h30
  text "PN: QDS10232_AVL (V0.5)" at 2880.3,3399.76 h30
  text "BOTTOM SILKSCREEN" at 5614,621 h65
Top Paste:
  text "TOP SOLDER PAST" at 4302,768 h65
Bottom Paste:
  text "BOTTOM SOLDER PAST" at 5603,770 h65
Top Solder:
  text "TOP SOLDERMASK" at 4292,467 h65
Bottom Solder:
  circle w110: c2609,277.56 r50
  circle w110: c249,277.56 r50
  text "BOTTOM SOLDERMASK" at 5608,466 h65
Dimension:
  lines w6: 379,1206.56 379,1207.56 379,1107.56 579,1107.56
Outline:
  lines w10: 4145.52,576.49 6895.52,576.49 ; 4145.52,726.49 6895.52,726.49 ; 4145.52,876.49 6895.52,876.49 ; 4145.52,1026.49 6895.52,1026.49 ; 4145.52,1176.49 6895.52,1176.49 ; 4145.52,1326.49 6895.52,1326.49 ; 4145.52,1476.49 6895.52,1476.49 ; 4145.52,1626.49 6895.52,1626.49 ; 4145.52,1776.49 6895.52,1776.49 ; 4145.52,2051.75 6895.52,2051.75 ; 4145.52,2226.75 6895.52,2226.75 ; 4145.52,2351.75 6895.52,2351.75 ; 4145.52,2476.75 6895.52,2476.75 ; 4145.52,2601.75 6895.52,2601.75 ; 4145.52,2726.75 6895.52,2726.75 ; 4145.52,2851.75 6895.52,2851.75 ; 4145.52,2976.75 6895.52,2976.75 ; 4145.52,3101.75 6895.52,3101.75 ; 4145.52,3351.75 6895.52,3351.75 ; 4895.71,2101.75 4895.71,3351.75 ; 5520.52,426.49 5520.52,1776.49 ; 6895.52,426.67 4145.52,426.67 ; 4145.52,426.67 4145.52,-503.34 6895.85,-503.34 6895.85,426.67 4145.52,426.67 ; 4145.52,2101.75 4145.52,426.49 6895.52,426.49 6895.52,2101.75 ; 4145.52,2101.75 6895.52,2101.75 ; 4145.52,2101.75 4145.52,4501.75 6895.52,4501.75 6895.52,2101.75 ; -121,-120 -121,3679 3379,3679 3379,-120 -121,-120
  text "Title:" at 4517.44,3205.16 h75
  text "Lat_Parallel_AVA_V2_Rev 0.1" at 5166.37,3192.06 h65
  text "Customer:" at 4323.95,3014.89 h65
  text "Contact:" at 4407.95,2883.89 h65
  text "CUST P/N#:" at 4245.95,2759.89 h65
  text "JOB#:" at 4530.05,2515.68 h65
  text "QDS10232_AVL (V0.5)" at 5023.08,2512.36 h65
  text "ENG./Designer:" at 4222.95,2390.89 h65
  text "AVAL" at 5029.58,2383.68 h65
  text "Scale:" at 4535.95,2262.89 h65
  text "1 TO 1" at 5029.58,2258.68 h65
  text "View:" at 4547.44,2135.16 h65
  text "TOP VIEW" at 5029.58,2133.68 h65
  text "DATE PLOTTED:" at 4307.25,1867.43 h65
  text ".Print_Date" at 5634.05,1860.73 h65
  text "PADMASTER" at 4259.58,1663.84 h65
  text "DRILLMASTER" at 5634.58,1663.84 h65
  text "PROPRIETARY NOTICE" at 4653.37,277.07 h100
  text "THIS DOCUMENT/FILE AND THE TECHNICAL" at 4318.03,148.08 h75
  text "DATA HEREIN DISCLOSED ARE PROPRIETARY" at 4321.93,23.7 h75
  text "TO Q DESIGN AND SHALL NOT BE DUPLICATED" at 4299.04,-104.27 h75
  text "USED, RELEASED, OR DISCLOSED IN" at 4316.87,-226.82 h75
  text "WHOLE OR IN PART WITHOUT EXPRESSED" at 4315.5,-347.32 h75
  text "WRITTEN PERMISSION." at 4322.12,-468.28 h75
Mechanical:
  lines w5: 479,1787.87 479,1807.56 ; 479,2687.87 479,2707.56 ; 1377.03,1187.28 1377.03,1202.05 ; 2379,1287.87 2379,1307.56 ; 2379,2147.87 2379,2167.56
  lines w10: 1314,2247.56 1384,2247.56 ; 1384,2177.56 1384,2247.56 ; 1384,2317.56 1384,2247.56 ; 1454,2247.56 1384,2247.56 ; 379,1207.56 379,3257.56 2479,3257.56 2479,1207.56 1969,1207.56 1869,1107.56 579,1107.56 479,1207.56 379,1207.56 ; 674,3257.56 2199,3257.56 674,3257.56 ; 688.17,2062.36 959.83,2062.36 959.83,2412.76 688.17,2412.76 688.17,2062.36
Mechanical 9:
  lines w10: 1629,1856 1629,2657.56 1629,3130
